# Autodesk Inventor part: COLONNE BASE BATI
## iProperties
Created: 2004-11
Part Number: COLONNE BASE BATI
Document SubType Name: Modeling
Designer: Bruno
Manufacturer: Standard
Standards Organization: Custom
Author: Bruno
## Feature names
1. Base1
